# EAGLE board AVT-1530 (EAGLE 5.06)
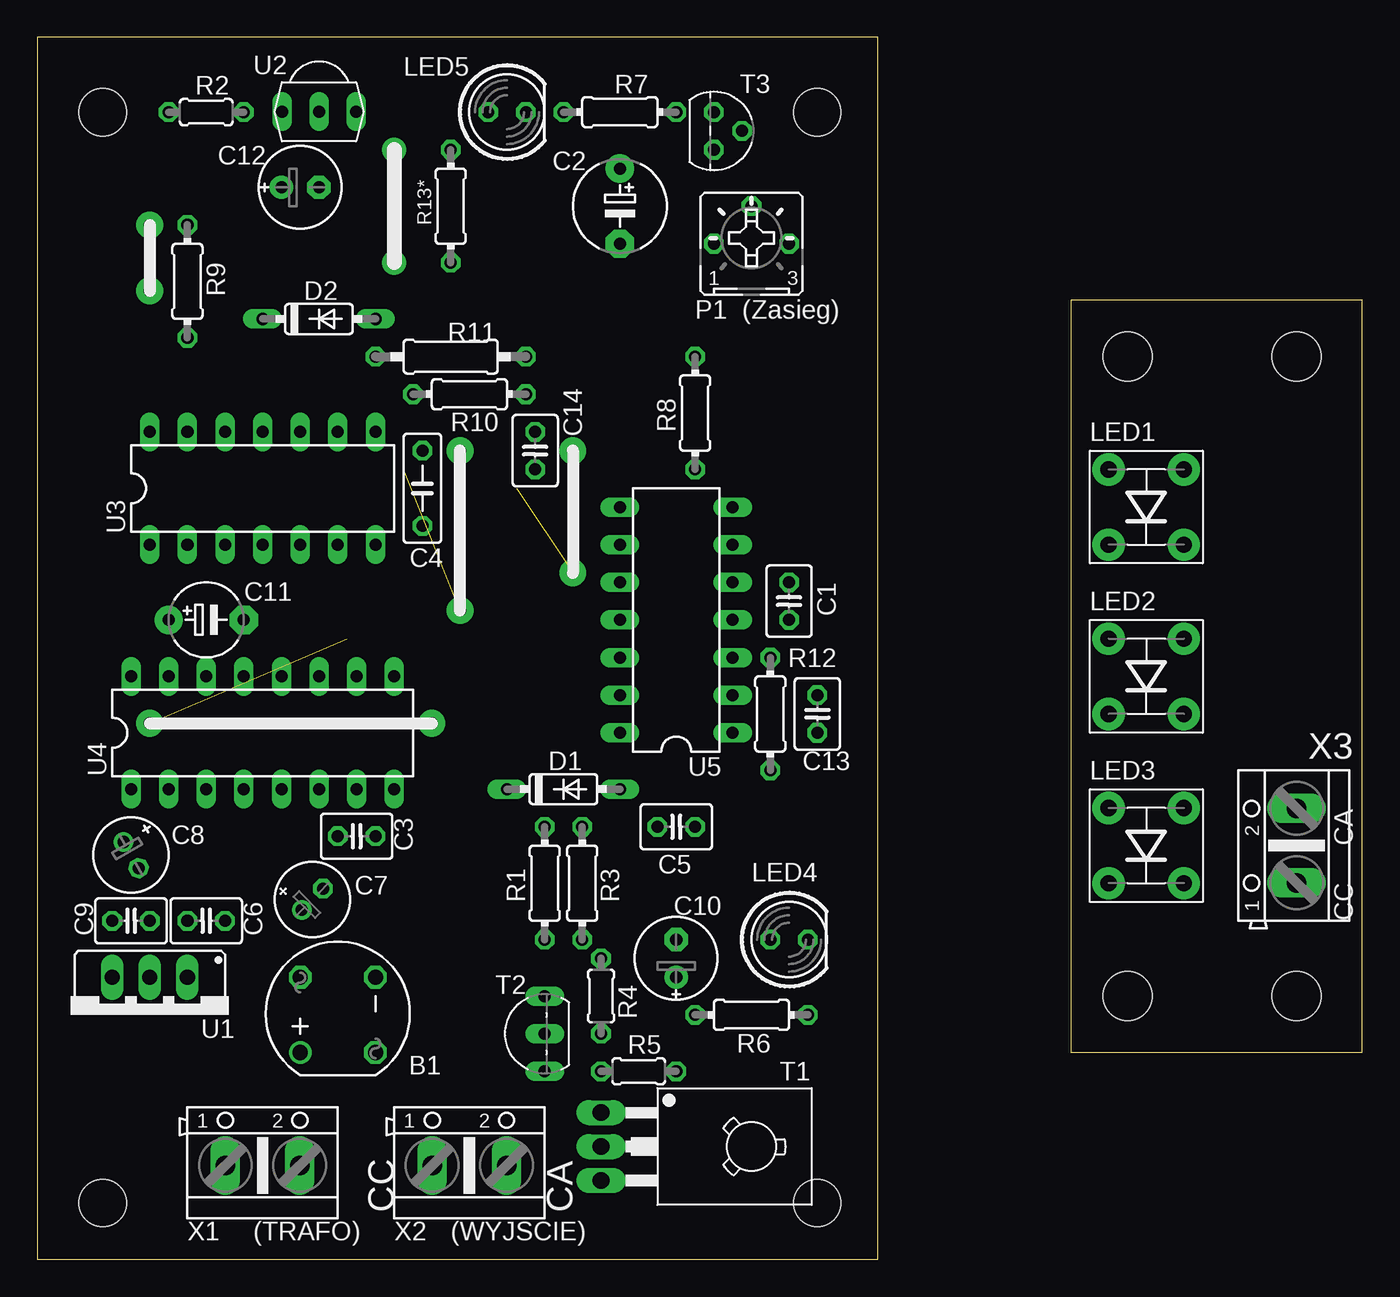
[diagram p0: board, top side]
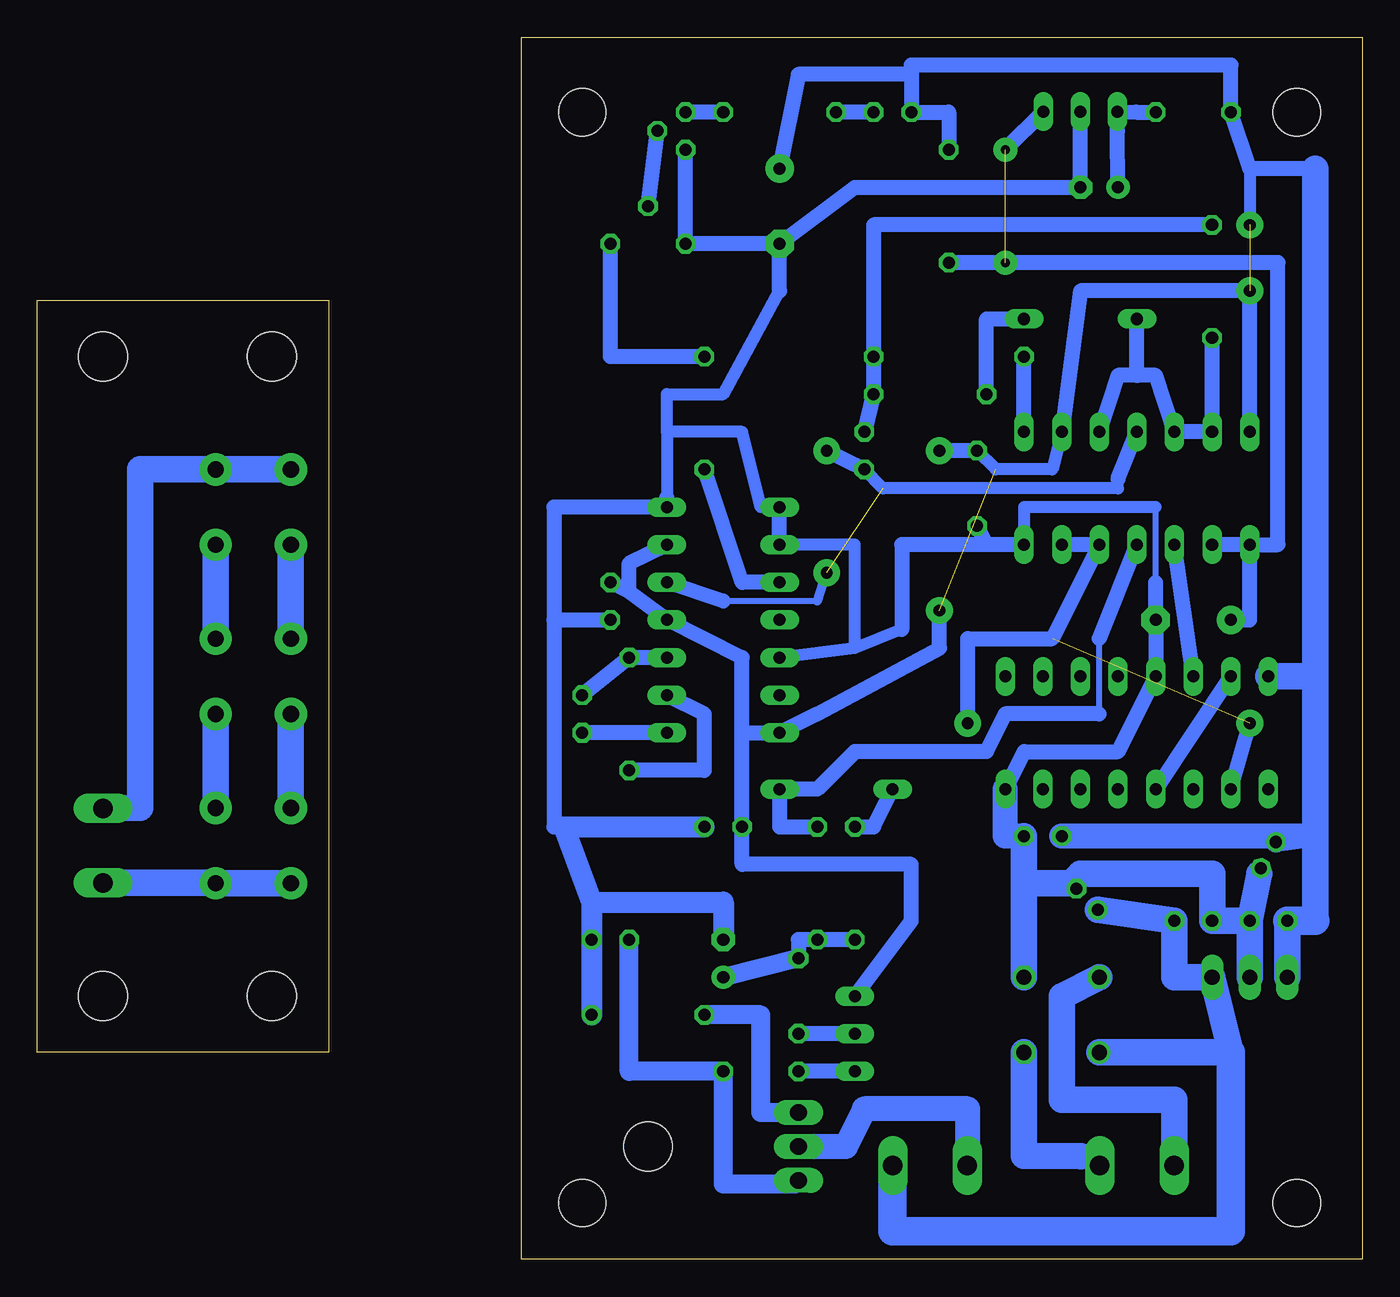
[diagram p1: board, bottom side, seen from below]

Size 89.53 x 82.54 mm. Coordinates in mm from the lower left corner, seen from the top.
Outline: 0,0 56.82,0 56.82,82.54 0,82.54 0,0
Outline: 69.85,13.97 89.53,13.97 89.53,64.77 69.85,64.77 69.85,13.97
Copper layers (1*16): Top 0.035mm / dielectric 1.5mm / Bottom 0.035mm
Design rules "default *": minimum track width 20mil, minimum drill 20mil, track to track 8mil, track to pad 8mil, pad to pad 8mil, via to via 8mil, smd to smd 8mil, copper to edge 40mil, drill to drill 8mil, minimum pad ring 10mil, minimum via ring 20mil, stop-mask expansion 4mil, vias tented up to drill 0mil, thermal gap 10mil
Holes 3.2 mm at 4.45,3.81 52.7,3.81 4.45,77.47 52.7,77.47
Holes 3.3 mm at 73.66,17.78 85.09,17.78 85.09,60.96 73.66,60.96

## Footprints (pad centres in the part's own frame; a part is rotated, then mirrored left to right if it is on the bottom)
RB1A = drill 1.016 round: + -2.54,2.54 | drill 1.016 octagon: - 2.54,-2.54; AC1 2.54,2.54; AC2 -2.54,-2.54
C025-030X050 = drill 0.813 octagon: 1 -1.27,0; 2 1.27,0
E5-6 = drill 0.813 pad 1.905 round: + -2.54,0 | drill 0.813 pad 1.905 octagon: - 2.54,0
C050-025X075 = drill 0.813 octagon: 1 -2.54,0; 2 2.54,0
E2-5 = drill 0.813 pad 1.27 round: + -1.016,0 | drill 0.813 pad 1.27 octagon: - 1.016,0
E2,5-6E = drill 0.813 pad 1.575 round: + -1.27,0 | drill 0.813 pad 1.575 octagon: - 1.27,0
E5-5 = drill 0.813 pad 1.905 round: + -2.54,0 | drill 0.813 pad 1.905 octagon: - 2.54,0
DO35-7 = drill 0.813 long: A 3.81,0; C -3.81,0
LED_FLUX = drill 1.1 pad 2.184 round: A1 2.54,2.54; A2 -2.54,2.54; C1 2.54,-2.54; C2 -2.54,-2.54
LED5MM = drill 0.813 octagon: A -1.27,0; K 1.27,0
B25P = drill 0.813 octagon: A -2.54,0; E 2.54,0; S 0,2.54
0204/7 = drill 0.813 octagon: 1 -3.81,0; 2 3.81,0
0204/5 = drill 0.813 octagon: 1 -2.54,0; 2 2.54,0
0207/10 = drill 0.813 octagon: 1 -5.08,0; 2 5.08,0
TO126 = drill 1.118 long: 1 -2.286,-5.08; 2 0,-5.08; 3 2.286,-5.08 | hole 3.302: 0,5.08
TO92-EBC = drill 0.813 long: B 0,-1.27; C -2.54,-1.27; E 2.54,-1.27
TO92 = drill 0.813 octagon: 1 1.27,0; 2 0,1.905; 3 -1.27,0
78XXS = drill 1.016 long: GND 0,-2.54; IN -2.54,-2.54; OUT 2.54,-2.54
TSOP18XX = drill 0.813 long: GND -0.001,-0.027; OUT -2.501,-0.027; VCC 2.499,-0.027
DIL14 = drill 0.813 long: 1 -7.62,-3.81; 2 -5.08,-3.81; 3 -2.54,-3.81; 4 0,-3.81; 5 2.54,-3.81; 6 5.08,-3.81; 7 7.62,-3.81; 8 7.62,3.81; 9 5.08,3.81; 10 2.54,3.81; 11 0,3.81; 12 -2.54,3.81; 13 -5.08,3.81; 14 -7.62,3.81
DIL16 = drill 0.813 long: 1 -8.89,-3.81; 2 -6.35,-3.81; 3 -3.81,-3.81; 4 -1.27,-3.81; 5 1.27,-3.81; 6 3.81,-3.81; 7 6.35,-3.81; 8 8.89,-3.81; 9 8.89,3.81; 10 6.35,3.81; 11 3.81,3.81; 12 1.27,3.81; 13 -1.27,3.81; 14 -3.81,3.81; 15 -6.35,3.81; 16 -8.89,3.81
AK500/2 = drill 1.321 long: 1 -2.515,0; 2 2.515,0

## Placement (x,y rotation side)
B1  mostek 1A  [RB1A]  20.32,16.51 90 top
C1  100n  [C025-030X050]  50.8,44.45 270 top
C2  100u  [E5-6]  39.37,71.12 270 top
C3  100n  [C025-030X050]  21.59,28.58 0 top
C4  100n  [C050-025X075]  26.03,52.07 270 top
C5  100n  [C025-030X050]  43.18,29.21 0 top
C6  100n  [C025-030X050]  11.43,22.86 180 top
C7  100u  [E2-5]  18.6,24.32 45 top
C8  100u  [E2-5]  6.35,27.3 300 top
C9  100n  [C025-030X050]  6.35,22.86 0 top
C10  220u  [E2,5-6E]  43.18,20.32 90 top
C11  10u  [E5-5]  11.43,43.18 0 top
C12  4,7u  [E2,5-6E]  17.78,72.39 0 top
C13  1n MKT  [C025-030X050]  52.7,36.83 270 top
C14  100n MKT  [C025-030X050]  33.66,54.61 270 top
D1  1N4148  [DO35-7]  35.56,31.75 0 top
D2  1N4148  [DO35-7]  19.05,63.5 0 top
LED1  LED SuperFLUX biala ciepla  [LED_FLUX]  74.93,50.8 0 top
LED2  LED SuperFLUX biala ciepla  [LED_FLUX]  74.93,39.37 0 top
LED3  LED SuperFLUX biala ciepla  [LED_FLUX]  74.93,27.94 0 top
LED4  LED zolta  [LED5MM]  50.8,21.59 0 top
LED5  LD271  [LED5MM]  31.75,77.47 0 top
P1  1M  [B25P]  48.26,68.58 0 top
R1  22k  [0204/7]  34.29,25.4 90 top
R2  220R  [0204/5]  11.43,77.47 180 top
R3  47k  [0204/7]  36.83,25.4 90 top
R4  1k  [0204/5]  38.1,17.78 270 top
R5  1k  [0204/5]  40.64,12.7 0 top
R6  68R  [0204/7]  48.26,16.51 180 top
R7  68R  [0204/7]  39.37,77.47 180 top
R8  1k  [0204/7]  44.45,57.15 90 top
R9  220k  [0204/7]  10.16,66.04 270 top
R10  2,7k  [0204/7]  29.21,58.42 0 top
R11  10k  [0207/10]  27.94,60.96 180 top
R12  5,6k  [0204/7]  49.53,36.83 90 top
R13*  1k  [0204/7]  27.94,71.12 90 top
T1  BD139  [TO126]  43.18,7.62 270 top
T2  BC558  [TO92-EBC]  33.02,15.24 90 top
T3  BC547A  [TO92]  45.72,76.2 270 top
U1  7805  [78XXS]  7.62,16.51 180 top
U2  TSOP1838  [TSOP18XX]  19.05,77.47 180 top
U3  4093N  [DIL14]  15.24,52.07 0 top
U4  4017N  [DIL16]  15.24,35.56 0 top
U5  4047N  [DIL14]  43.18,43.18 90 top
X1  ARK2  [AK500/2]  15.24,6.35 0 top
X2  ARK2  [AK500/2]  29.21,6.35 0 top
X3  ARK2  [AK500/2]  85.09,27.94 90 top

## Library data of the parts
B1 = rectifier
C1-C14 R1-R12 R13* = rcl
D1 D2 = diode
LED1-LED3 = LED SuperFlux
LED4 LED5 = led
P1 = pot
T1 = transistor-neu-to92
T2 = transistor-pnp
T3 = transistor-npn
U1 = v-reg
U2 = tsop
U3-U5 = 40xx
X1-X3 = con-ptr500

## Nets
+5V: C1.1 C2.+ C3.1 C4.1 C5.1 C8.+ C9.1 LED5.A R2.2 R13*.2 T2.E U1.OUT U3.9 U3.14 U4.16 U5.4 U5.6 U5.14
GND: B1.- C1.2 C2.- C3.2 C4.2 C5.2 C6.2 C7.- C8.- C9.2 C10.- C11.- C12.- LED4.K P1.A R6.1 T3.1 U1.GND U2.GND U3.7 U4.8 U4.13 U5.7 U5.8 U5.9 U5.12
N$1: LED1.A1 LED1.A2 X3.2
N$2: B1.AC1 X1.1
N$3: R5.1 T2.C
N$4: R4.2 T2.B
N$5: B1.AC2 X1.2
N$6: U4.4 U4.15
N$7: D2.C R9.2 U3.10 U3.12 U3.13
N$8: U3.3 U4.14
N$9: LED1.C1 LED2.A1
N$10: LED1.C2 LED2.A2
N$11: R7.1 T3.3
N$12: U3.5 U3.6 U4.2
N$13: C13.1 R12.2 U5.3
N$14: C13.2 U5.1
N$15: R12.1 U5.2
N$16: P1.S T3.2
N$17: R8.1 U5.10
N$18: R11.2 U3.8
N$19: C14.2 U3.11 U5.5
N$21: LED5.K R7.2
N$22: LED4.A R5.2 T1.3
N$23: D1.A R3.2 U3.4
N$25: P1.E R8.2
N$26: C10.+ R1.1 R3.1 R4.1
N$27: C14.1 R9.1 R10.2 R11.1
N$28: D2.A R10.1
N$29: R6.2 T1.1
N$30: B1.+ C6.1 C7.+ U1.IN X2.2
N$32: D1.C R1.2
N$33: C11.+ R13*.1 U2.OUT U3.1 U3.2
N$36: LED2.C1 LED3.A1
N$37: LED2.C2 LED3.A2
N$38: LED3.C1 LED3.C2 X3.1
N$39: T1.2 X2.1
N$69: C12.+ R2.1 U2.VCC

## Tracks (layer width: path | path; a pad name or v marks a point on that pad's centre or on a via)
+5V  (via drill 0.8)  (2 unrouted)
  Bottom 0.813: C4.1 24.77,53.34 20.95,53.34 U3.9 | 7.62,73.66 v7.62,69.85
  Bottom 1.016: 41.91,35.56 U5.14 36.83,36.83 28.58,41.27 v28.58,43.81 | 49.53,45.09 U5.4 41.91,40.64 41.91,35.56 | 49.53,45.09 49.53,46.99 U5.6 | 30.48,80.01 30.48,80.64 8.89,80.64 R2.2 7.62,73.66 3.17,73.66 | 30.48,80.01 LED5.A 27.94,77.47 R13*.2 | T2.E 30.48,22.86 30.48,26.67 41.91,26.67 C5.1 41.91,35.56 | U3.9 19.05,65.41 v7.62,65.41 U3.14 | C2.+ 38.1,80.01 30.48,80.01 | 49.53,45.09 C1.1 | C4.1 v28.58,54.61
  Bottom 1.422: 3.17,28.58 C8.+
  Bottom 1.676: 3.17,28.58 C3.1
  Bottom 1.778: 3.17,39.37 U4.16 | 3.17,39.37 3.17,73.66 | U1.OUT C9.1 | 3.17,22.86 3.17,28.58 3.17,39.37
  Bottom 1.93: C9.1 3.17,22.86
GND
  Bottom 0.406: 13.97,45.72 13.97,50.8
  Bottom 0.813: 13.97,50.8 22.86,50.8 U3.7 | U5.9 34.29,48.26 34.29,41.27 | 31.12,42.55 34.29,41.27 | 34.29,41.27 U5.12 | 39.37,65.41 43.18,58.42 46.99,58.42 46.99,55.88 | 46.99,55.88 46.99,51.43 | 46.99,55.88 41.91,55.88 40.64,50.8 U5.8
  Bottom 1.016: U5.9 U5.8 | C12.- | C12.- U2.GND | T3.1 P1.A C2.- | U4.8 22.86,34.29 16.51,34.29 U4.13 C11.- 13.97,45.72 | 54.61,43.18 54.61,29.21 53.98,29.21 | 54.61,43.18 54.61,50.8 U5.7 46.99,51.43 | C12.- 34.29,72.39 C2.- | 6.99,26.03 C8.- | 54.61,43.18 C1.2 | 39.37,65.41 C2.- | U3.7 25.4,48.26 | 25.4,48.26 C4.2 | 19.69,25.4 C7.- | 25.4,48.26 31.12,48.26 31.12,42.55
  Bottom 1.422: R6.1 LED4.K 52.07,24.13 | C10.- 43.18,24.13 52.07,24.13 | C5.2 53.98,29.21 52.07,24.13
  Bottom 1.676: C3.2 24.13,28.58 U4.8
  Bottom 1.778: U1.GND C9.2 | C9.2 C6.2 10.16,26.03 19.05,26.03 19.69,25.4 22.86,25.4 | C9.2 6.99,26.03 | 22.86,25.4 B1.- | 22.86,25.4 C3.2
N$1
  Bottom 1.778: X3.2 82.55,30.48 82.55,53.34 LED1.A1 LED1.A2
N$2
  Bottom 1.016: X1.1 12.72,6.96
  Bottom 1.27: 12.72,6.96 12.7,6.99
  Bottom 1.778: 12.7,6.99 12.7,10.79 20.32,10.79 20.32,17.78 B1.AC1
N$3
  Bottom 1.016: T2.C R5.1
N$4
  Bottom 1.016: T2.B R4.2
N$5
  Bottom 1.27: X1.2 19.02,6.96
  Bottom 1.778: 19.02,6.96 22.86,6.99 B1.AC2
N$6
  Bottom 1.016: U4.4 U4.15
N$7
  Bottom 1.016: R9.2 U3.13 U3.12 13.97,59.69 15.24,59.69 | 15.24,59.69 D2.C | 15.24,59.69 16.51,59.69 U3.10
N$8
  Bottom 1.016: U4.14 U3.3
N$9
  Bottom 1.778: LED2.A1 LED1.C1
N$10
  Bottom 1.778: LED2.A2 LED1.C2
N$11
  Bottom 1.016: R7.1 T3.3
N$12  (via drill 0.8)  (1 unrouted)
  Bottom 1.016: U4.2 v7.62,36.2 | v26.67,36.2 26.67,41.91 20.95,41.91 U3.5 U3.6
N$13
  Bottom 1.016: C13.1 R12.2 U5.3
N$14
  Bottom 1.016: U5.1 C13.2
N$15
  Bottom 1.016: U5.2 44.45,36.83 44.45,33.02 R12.1
N$16
  Bottom 1.016: P1.S T3.2
N$17
  Bottom 1.016: R8.1 41.91,45.72 U5.10
N$18
  Bottom 1.016: U3.8 R11.2
N$19  (via drill 0.8)  (1 unrouted)
  Bottom 0.406: 36.83,44.45 43.18,44.45
  Bottom 0.61: 36.83,44.45 v36.2,46.35
  Bottom 0.813: 16.51,52.7 16.51,52.07 32.38,52.07 C14.2
  Bottom 1.016: 16.51,52.7 U3.11 | 43.18,44.45 U5.5 | C14.2 v36.2,54.61
N$21
  Bottom 1.016: LED5.K R7.2
N$22
  Bottom 1.016: T1.3 38.35,5.08
  Bottom 1.27: 38.35,5.08 43.18,5.08 R5.2 49.53,12.7 LED4.A
N$23
  Bottom 0.406: 17.78,36.83 17.78,41.91
  Bottom 1.016: 17.78,41.91 U3.4 | 17.78,36.83 24.13,36.83 25.4,34.29 34.29,34.29 36.83,31.75 D1.A 39.37,29.21 R3.2
N$25
  Bottom 1.016: P1.E 50.8,60.96 R8.2
N$26
  Bottom 1.016: R1.1 R3.1 38.1,21.59 R4.1
  Bottom 1.27: R4.1 C10.+
N$27
  Bottom 1.016: R9.1 33.02,69.85 R11.1 R10.2 C14.1
N$28
  Bottom 1.016: R10.1 25.4,63.5 D2.A
N$29
  Bottom 1.27: T1.1 40.64,9.91 40.64,16.51 R6.2
N$30
  Bottom 1.778: C7.+ C6.1 12.7,19.05 U1.IN 8.89,13.97 B1.+ | 31.75,6.35 X2.2
  Bottom 1.93: 31.75,6.35 31.75,1.91 8.89,1.91 8.89,13.97
N$32
  Bottom 1.016: R1.2 33.02,29.21 D1.C
N$33  (via drill 0.6)  (1 unrouted)
  Bottom 1.016: 21.59,77.5 U2.OUT 24.13,74.96 v24.13,74.93 | U3.1 U3.2 | U3.1 5.71,48.26 5.71,67.31 v24.13,67.31 R13*.1 | C11.+ 7.62,43.18 U3.1
N$36
  Bottom 1.778: LED3.A1 LED2.C1
N$37
  Bottom 1.778: LED3.A2 LED2.C2
N$38
  Bottom 1.778: LED3.C2 LED3.C1 78.11,25.42 X3.1
N$39
  Bottom 1.676: 26.67,6.99 26.67,10.16 33.66,10.16 34.92,7.62 T1.2
  Bottom 1.778: X2.1 26.67,6.99
N$69
  Bottom 1.016: C12.+ 16.55,76.2 U2.VCC 15.28,77.47 R2.1

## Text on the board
tPlace: CC | CA
tNames: U2 | (Zasieg) | CA | CC | (TRAFO) | (WYJSCIE)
